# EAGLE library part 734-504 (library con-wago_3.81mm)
Serie 734, Federleiste mit geraden Einlötstiften / Series 734, Female connector with straight solder pins Polzahl / Pole No.: 4 Bemessungsspannung / Rated Voltage: 160 V Nennstrom / Nominal Current: 10 A Lötstiftlänge: / Solder Pin Length: 3.8 mm Farbe / Color: orange / orange Stand: 01.01.2012. Die jeweils aktuellen Daten zu diesem Artikel finden Sie in unserem Produktkatalog, den Sie unter www.wago.com einsehen können. As of: 01/01/2012. Please find the newest data for this article in our product catalogue, which can be viewed under www.wago.com.
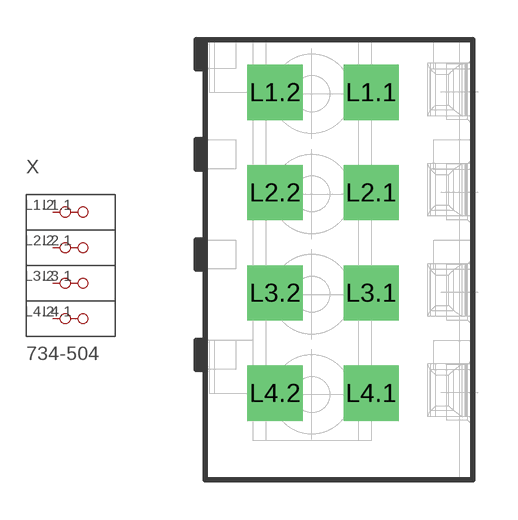
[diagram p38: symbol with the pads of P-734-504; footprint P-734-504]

Designator prefix X

## 734-504  [P-734-504]
L1.1  P1.1
L1.2  P1.2
L2.1  P2.1
L2.2  P2.2
L3.1  P3.1
L3.2  P3.2
L4.1  P4.1
L4.2  P4.2

## Footprint P-734-504 (pad centres in mm)
drill 1.4 square: L1.1 1.294,6.36; L1.2 -2.356,6.36; L2.1 1.294,2.55; L2.2 -2.356,2.55; L3.1 1.294,-1.26; L3.2 -2.356,-1.26; L4.1 1.294,-5.07; L4.2 -2.356,-5.07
